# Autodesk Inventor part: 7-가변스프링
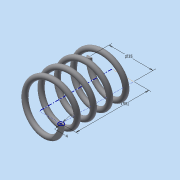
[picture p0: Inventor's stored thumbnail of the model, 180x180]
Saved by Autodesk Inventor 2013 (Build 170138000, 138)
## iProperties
Created: 2015-03
Part Number: 7-가변스프링
Material: 강철, 탄소
Document SubType Name: Modeling
Designer: Administrator
Density: 7.87 g/cm^3
Mass: 48.2172 g
Surface Area: 62.1432 cm^2
Volume: 6.12671 cm^3
Author: Administrator
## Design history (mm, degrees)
sketch "스케치1"
  geometry: L1 (0, 0)-(17.5, 0); L2 (17.5, 0)-(17.5, 43.5); L3 (17.5, 43.5)-(0, 43.5); L4 (0, 43.5)-(0, 0); C1 r 2 at (17.5, 0)
  constraints: 8 end point, 2 parallel, 1 centre point, 1 coincident, 1 horizontal, 1 perpendicular
  dimensions: "d0" = 35 diameter of L2 L4; "d2" = 43.5 distance of L1.end L2.end (derived); "d3" = 4 diameter of C1
feature "코일1" pitch "d4" = 10; turns "d6" = 4.5; dims "d5" = 43.5 (= d2), "d7" = 0, angle "d8" = 90 deg, angle "d9" = 90 deg, "d10" = 0, "d11" = 0
node "작업 평면1"
sketch "스케치2"
  geometry: L1 (-19.5, 0)-(-15.5, 0) reference; L2 (-19.5, 0)-(-15.5, 0) reference; 1 further point
  constraints: 2 horizontal alignment
extrude "돌출1" cut sketch "스케치2" stored distance "d13" = 10; taper "d14" = 0 deg
node "작업 평면2"
sketch "스케치3"
  geometry: L1 (-19.5, 0)-(-15.5, 0) reference; 1 further point
  constraints: 1 horizontal alignment
extrude "돌출2" cut sketch "스케치3" stored distance "d16" = 10; taper "d17" = 0 deg
node "솔리드1"
node "절단 모서리 투영1"
node "절단 모서리 투영2"
node "절단 모서리 투영3"
other parameters: "d12" = 0, "d15" = -43.5 (= -d2)
